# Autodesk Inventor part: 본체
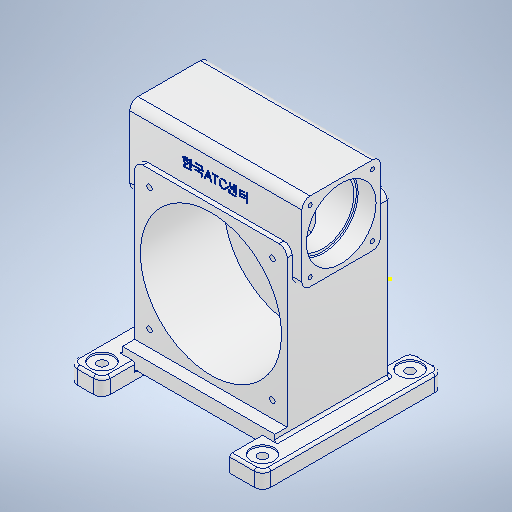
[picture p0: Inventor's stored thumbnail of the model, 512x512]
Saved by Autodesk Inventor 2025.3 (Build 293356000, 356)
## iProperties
Created: 2025-06
Part Number: 본체
Material: 알루미늄 6061
Document SubType Name: Modeling
Designer: PC-10
Density: 2.7 g/cm^3
Appearance: 알루미늄 - 평지
Mass: 7613.17 g
Surface Area: 3465.54 cm^2
Volume: 2819.69 cm^3
Author: PC-10
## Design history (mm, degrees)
sketch "스케치1"
  geometry: L1 (-93, -94.5)-(93, -94.5); L2 (93, -94.5)-(93, 94.5); L3 (93, 94.5)-(-93, 94.5); L4 (-93, 94.5)-(-93, -94.5); L5 (-93, -94.5)-(93, 94.5); L6 (93, -94.5)-(-93, 94.5); 1 further point
  constraints: 12 end point, 2 midpoint, 2 parallel, 1 horizontal, 1 perpendicular
  dimensions: "d0" = 186 distance of L2.end L3.end; "d1" = 189 distance of L1.end L2.end
extrude "돌출1" new body sketch "스케치1" distance "d2" = 125; taper "d3" = 0 deg
node "작업 평면2"
sketch "스케치3"
  geometry: C1 r 86 at (0, 0); 1 further point
  constraints: 1 centre point, 1 coincident
  dimensions: "d8" = 172 diameter of C1
extrude "돌출2" cut sketch "스케치3" distance "d9" = 102; taper "d10" = 0 deg
sketch "스케치4"
  geometry: L1 (-86, 23)-(86, 23) reference; L2 (94.5, 0)-(-94.5, 0) reference; L3 (0, 0)-(0, -17.431); L4 (31, 23)-(31, 7); L5 (31, 7)-(27, 7); L6 (27, 7)-(27, 4); L7 (27, 4)-(0, 4); L8 (0, 4)-(0, 23); 1 further point
  constraints: 12 end point, 3 perpendicular, 2 midpoint, 2 vertical, 1 point on line, 1 vertical alignment
  dimensions: "d11" = 62 diameter of L4 L3; "d12" = 54 diameter of L6 L3; "d13" = 3 distance between parallel lines of L5 L7; "d14" = 16 distance of L4.start L4.end
revolve "회전1" sketch "스케치4" stored, may be unused: angle "d15" = 90 deg
sketch "스케치6"
  geometry: L1 (148, 119)-(52, 119); L2 (52, 119)-(52, 23); L3 (52, 23)-(148, 23); L4 (148, 23)-(148, 119); L5 (-86, 23)-(86, 23) reference; L6 (94.5, 0)-(94.5, 125) reference; L7 (-94.5, 125)-(94.5, 125) reference; 4 further points
  constraints: 8 end point, 3 midpoint, 2 parallel, 1 horizontal, 1 horizontal alignment, 1 perpendicular
  dimensions: "d20" = 96 distance of L3.end L1.start; "d87" = 100 horizontal distance of point (0, 125) point (100, 119); "d89" = 96 distance of L1.start L1.end
extrude "돌출4" join sketch "스케치6" stored distance "d23" = 210; taper "d24" = 0 deg
sketch "스케치7"
  geometry: L1 (119, 52)-(119, 148) reference; L2 (119, 148)-(23, 148) reference; L3 (23, 148)-(23, 52) reference; L4 (23, 52)-(119, 52) reference; 4 further points
  constraints: 2 midpoint, 1 horizontal alignment, 1 vertical alignment
hole "구멍1" sketch "스케치7" at (71, 100) diameter "d25" = 77; stored, may be unused: countersink angle "d29" = 90 deg, drill point angle "d31" = 118 deg; dims "d26" = 13, "d27" = 85, "d28" = 23, "d30" = 16
sketch "스케치8"
  geometry: C1 r 38.5 at (-71, 100) reference; C2 r 42.5 at (-71, 100); 1 further point
  constraints: 1 centre point, 1 coincident
  dimensions: "d32" = 85 diameter of C2
extrude "돌출5" cut sketch "스케치8" distance "d33" = 23; taper "d34" = 0 deg
node "작업 평면3"
sketch "스케치9"
  geometry: L1 (-68.498, 52)-(68.498, 52) reference; A1 r 86 centre (0, 0) between (68.498, 52) and (-68.498, 52) reference; 1 further point
extrude "돌출6" cut sketch "스케치9" distance "d36" = 102; taper "d37" = 0 deg
node "작업 평면5"
node "작업 평면6"
node "작업 평면7"
node "작업 평면8"
sketch "스케치10"
  geometry: L1 (198, -6)-(12, -6) reference; L2 (12, -6)-(198, -6); L3 (198, -6)-(198, -21); L4 (198, -21)-(12, -21); L5 (12, -21)-(12, -6); 2 further points
  constraints: 8 end point, 2 parallel, 1 horizontal, 1 perpendicular
  dimensions: "d40" = 15 distance of L4.end L1.end
extrude "돌출7" join sketch "스케치10" distance "d41" = 14; taper "d42" = 0 deg
sketch "스케치11"
  geometry: 1 further point
node "작업 평면10"
sketch "스케치14"
  geometry: L1 (119, 52)-(119, 148) reference; L2 (119, 148)-(23, 148) reference; L3 (23, 148)-(23, 52) reference; L4 (23, 52)-(119, 52) reference; L5 (33, 62)-(109, 62); L6 (109, 62)-(109, 138); L7 (109, 138)-(33, 138); L8 (33, 138)-(33, 62); L9 (33, 62)-(109, 138); L10 (109, 62)-(33, 138); C1 r 42.5 at (71, 100) reference; 5 further points
  constraints: 12 end point, 4 coincident, 2 midpoint, 2 parallel, 1 horizontal, 1 perpendicular
  dimensions: "d63" = 76 distance of L6.end L7.end; "d64" = 76 distance of L5.end L6.end
hole "구멍3" sketch "스케치14" at (109, 138), (33, 138), (33, 62), (109, 62) diameter "d65" = 4.917; stored, may be unused: countersink angle "d69" = 90 deg, drill point angle "d71" = 118 deg; dims "d66" = 12, "d67" = 28, "d68" = 2, "d70" = 14
node "작업 평면11"
sketch "스케치15"
  geometry: L1 (-75, -75)-(75, -75); L2 (75, -75)-(75, 75); L3 (75, 75)-(-75, 75); L4 (-75, 75)-(-75, -75); L5 (-75, -75)-(75, 75); L6 (75, -75)-(-75, 75); 5 further points
  constraints: 12 end point, 4 coincident, 2 midpoint, 2 parallel, 1 horizontal, 1 perpendicular
  dimensions: "d72" = 150 distance of L3.end L2.end; "d73" = 150 distance of L2.end L1.end
hole "구멍4" sketch "스케치15" at (75, 75), (75, -75), (-75, -75), (-75, 75) diameter "d74" = 6.647; stored, may be unused: countersink angle "d78" = 90 deg, drill point angle "d80" = 118 deg; dims "d75" = 16, "d76" = 4, "d77" = 2, "d79" = 18
fillet "모깎기1" dims "d81" = 10
sketch "스케치16"
  geometry: L1 (210, 10)-(0, 10) reference; 3 further points
  constraints: 1 midpoint, 1 vertical alignment, 1 other
  dimensions: "d84" = 30 distance from line of L1 point (105, -20)
feature "엠보싱1" sketch "스케치16" dims "d85" = 0.5, "d86" = 0
node "작업 평면14"
sketch "스케치20"
  geometry: L1 (-10, 0)-(176, 0) reference; L2 (176, 0)-(176, -125) reference; L3 (-10, -125)-(176, -125) reference; L4 (-10, 0)-(-10, -125) reference; L5 (176, -125)-(-10, -125); L6 (-10, -125)-(-10, -140); L7 (-10, -140)-(176, -140); L8 (176, -140)-(176, -125); 2 further points
  constraints: 8 end point, 2 parallel, 1 coincident, 1 horizontal, 1 perpendicular
  dimensions: "d93" = 15 distance of L7.end L2.end
extrude "돌출9" join sketch "스케치20" distance "d94" = 20; taper "d95" = 0 deg
sketch "스케치21"
  geometry: 1 further point
sketch "스케치22"
  geometry: L1 (12, -21)-(198, -21) reference; L2 (198, -21)-(198, -6) reference; L3 (12, -6)-(198, -6) reference; L4 (12, -6)-(12, -21) reference; 1 further point
extrude "돌출10" cut sketch "스케치22" distance "d96" = 5.5; taper "d97" = 0 deg
sketch "스케치23"
  geometry: 1 further point
node "작업 평면15"
sketch "스케치24"
  geometry: L1 (223, -147)-(183, -147); L2 (183, -147)-(183, 73); L3 (183, 73)-(223, 73); L4 (223, 73)-(223, -147); L5 (27, -147)-(-13, -147); L6 (-13, -147)-(-13, 73); L7 (-13, 73)-(27, 73); L8 (27, 73)-(27, -147); L9 (198, -107)-(198, 33) reference; 2 further points
  constraints: 16 end point, 4 parallel, 2 horizontal, 2 perpendicular, 1 midpoint, 1 point on line
  dimensions: "d99" = 220 distance of L3.end L1.start; "d101" = 236 distance between parallel lines of L6 L4; "d102" = 118 distance from line of point (105, 33) L4; "d103" = 110 distance from line of point (198, -37) L1; "d104" = 40 distance of L2.end L3.end; "d105" = 40 distance of L6.end L7.end; "d106" = 220 distance of L5.end L6.end
extrude "돌출11" join sketch "스케치24" distance "d107" = 20; taper "d108" = 0 deg
sketch "스케치25"
  geometry: L1 (27, 33)-(12, 33) reference; L2 (27, 33)-(27, 73) reference; L3 (27, 73)-(-13, 73) reference; L4 (-13, 73)-(-13, -147) reference; L5 (-13, -147)-(27, -147) reference; L6 (27, -147)-(27, -107) reference; L7 (12, -107)-(27, -107) reference; L8 (12, 33)-(12, -107) reference; L9 (198, 33)-(183, 33) reference; L10 (198, -107)-(198, 33) reference; L11 (183, -107)-(198, -107) reference; L12 (183, -107)-(183, -147) reference; L13 (183, -147)-(223, -147) reference; L14 (223, -147)-(223, 73) reference; L15 (223, 73)-(183, 73) reference; L16 (183, 73)-(183, 33) reference; L17 (12, -76)-(12, 0) reference; L18 (188, 33)-(22, 33) reference; L19 (12, 33)-(12, 10) reference; L20 (12, -76)-(12, -86) reference; L21 (12, -86)-(22, -86) reference; L22 (188, -86)-(22, -86) reference; L23 (188, -86)-(198, -86) reference; L24 (198, -86)-(198, -76) reference; L25 (198, 0)-(198, -76) reference; L26 (198, 0)-(198, 10) reference; L27 (198, 10)-(188, 10) reference; L28 (22, 10)-(188, 10) reference; L29 (22, 10)-(12, 10) reference; L30 (12, 10)-(12, 0) reference; L31 (12, 33)-(12, -107) reference; 8 further points
  constraints: 3 midpoint, 2 horizontal alignment, 1 vertical alignment
  dimensions: "d109" = 180 distance of point (7, 53) point (7, -127); "d110" = 196 distance of point (203, 53) point (7, 53); "d112" = 98 horizontal distance of point (105, 33) point (203, 53); "d113" = 196 distance of point (203, -127) point (7, -127); "d121" = 90 vertical distance of point (12, -37) point (7, -127)
hole "구멍5" sketch "스케치25" at (7, -127), (203, -127), (203, 53), (7, 53) diameter "d114" = 11; stored, may be unused: countersink angle "d118" = 90 deg, drill point angle "d120" = 118 deg; dims "d115" = 16, "d116" = 28, "d117" = 2, "d119" = 18
fillet "모깎기4" dims "d122" = 10
fillet "모깎기5" dims "d123" = 3
fillet "모깎기6" dims "d124" = 1
fillet "모깎기7" dims "d125" = 1.1
node "솔리드1"
mirror "미러1"
node "투영된 루프2"
node "투영된 루프3"
node "투영된 루프6"
node "투영된 루프10"
node "투영된 루프11"
node "투영된 루프12"
node "투영된 루프13"
feature "A9D066F2-1C7D-4E18-AEED-F7BC21143FA4" dims "d25" = 77, "d26" = 13, "d27" = 85, "d28" = 23, "d29" = 90 deg, "d30" = 16, "d31" = 118 deg
other parameters: "d7" = -123, "d39" = -189, "d44" = -271, "d92" = -206, "d98" = -271
